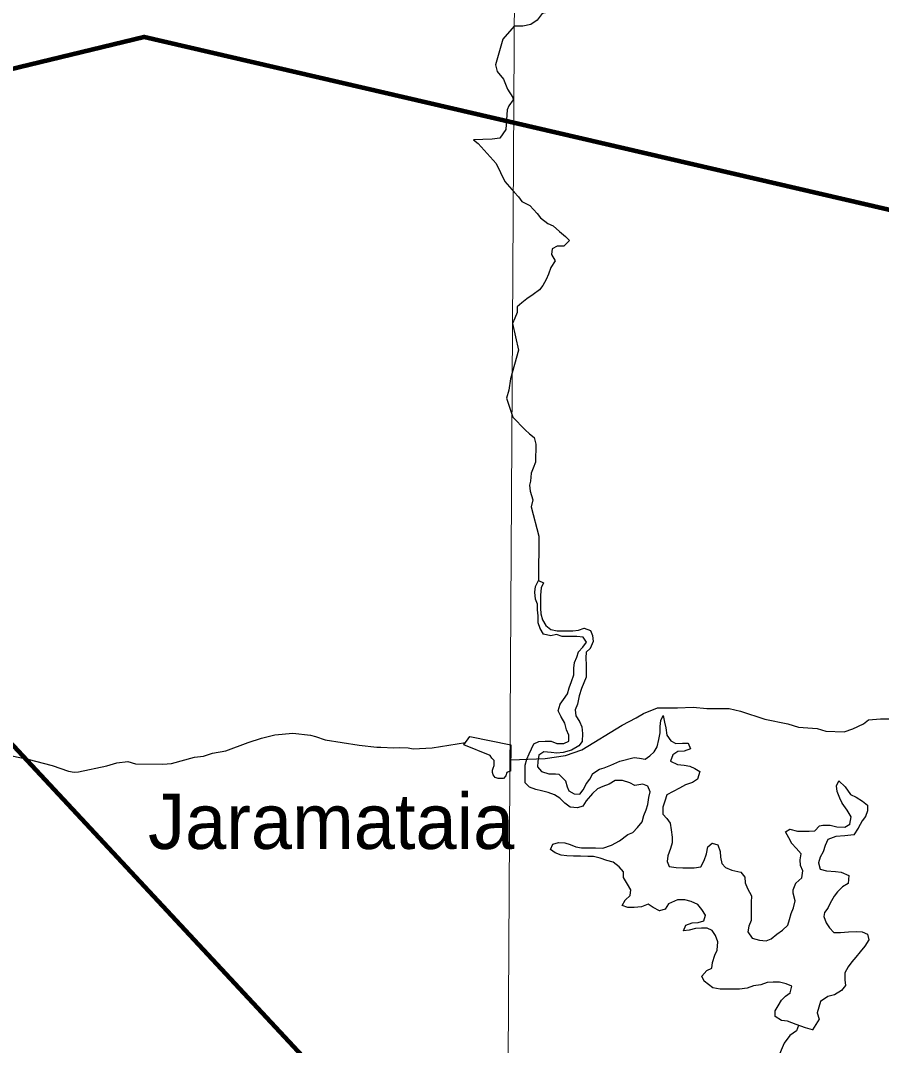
# Model space of a CAD drawing. Extents: x 553962 to 842807, y 8883888 to 9032388.
# Drawn here: x 715039 to 722813, y 8929001 to 8938264 of the extents above; entities that cross this region are included whole.
import ezdxf

# ---------------------------------------------------------------- set-up
doc = ezdxf.new("R2010")
doc.units = 0
doc.header["$LTSCALE"] = 200
for name, color, linetype, lineweight in [('1', 7, 'Continuous', 13), ('12', 7, 'Continuous', 25), ('21', 7, 'Continuous', 25), ('24', 7, 'Continuous', 25), ('9', 7, 'Continuous', 90)]:
    doc.layers.add(name, color=color, linetype=linetype, lineweight=lineweight)
doc.layers.add('41', color=7, linetype='Continuous')

msp = doc.modelspace()

# ---------------------------------------------------------------- linework, layer by layer
at = {"layer": '1'}
msp.add_lwpolyline([(719978.9, 9023574.5), (719561.6, 8949232.2), (719215.6, 8890710.6)], dxfattribs=at)
at = {"layer": '12'}
for points in [[(719465.7, 8931582), (719776.2, 8931594.6), (719960.1, 8931621.3), (720108, 8931671.9), (720470.6, 8931895.4), (720598.2, 8931961.4), (720664.5, 8932002), (720792.1, 8932052.7), (720970.4, 8932052.4), (721113, 8932057.2), (721235.3, 8932046.8), (721439, 8932046.4), (721540.8, 8932020.8), (721759.6, 8931949.1), (721968.3, 8931907.9), (722065, 8931877.2), (722233.1, 8931866.7), (722309.4, 8931841.1), (722477.5, 8931835.7), (722554, 8931861), (722651, 8931906.7), (722697, 8931942.3), (722804, 8931952.2), (722928.4, 8931953)], [(716324.2, 8931543.6), (716403.5, 8931548.6), (716611, 8931605.6), (716690.2, 8931616.7), (716773.7, 8931642.7), (716891.8, 8931664.4), (717093.4, 8931739.1), (717215.6, 8931777.9), (717335.2, 8931806.9), (717497.8, 8931823.2), (717656.3, 8931805.2), (717701.6, 8931794.1), (717788.3, 8931763.5), (718097.5, 8931715.5), (718256.9, 8931697.3), (718293.2, 8931696)], [(718293.2, 8931696), (718411.2, 8931691.7), (718463.6, 8931694.9), (718539.5, 8931689.8), (718584.8, 8931680.8), (718757, 8931689.8), (719057.1, 8931737.7)], [(714667.4, 8931678.5), (715103.5, 8931588.9), (715323.4, 8931530.2), (715472.8, 8931481.2), (715522.4, 8931471.9), (715561.6, 8931473.7), (715819.4, 8931527.1), (715907.5, 8931556.1), (716007, 8931568.4), (716078.4, 8931547.1), (716324.2, 8931543.6)]]:
    msp.add_lwpolyline(points, dxfattribs=at)
at = {"layer": '21'}
msp.add_lwpolyline([(719466.9, 8931717.9), (719464.5, 8931480.1), (719451.4, 8931477.4), (719431, 8931467.2), (719420.8, 8931436.5), (719400.5, 8931413.5), (719380.2, 8931413.5), (719352.2, 8931413.5), (719324.2, 8931423.7), (719306.3, 8931446.7), (719301.3, 8931467.1), (719301.2, 8931487.6), (719306.3, 8931508), (719316.5, 8931531.1), (719316.5, 8931554.1), (719316.5, 8931577.1), (719296.1, 8931597.5), (719278.3, 8931620.5), (719041.6, 8931717.6), (719097.6, 8931791.8)], close=True, dxfattribs=at)
at = {"layer": '24'}
for points in [[(720060.8, 8938559.8), (720055.8, 8938559.8), (719994.6, 8938534.7), (719948.5, 8938494.2), (719922.7, 8938443.5), (719881.3, 8938336.8), (719825.4, 8938342.2), (719749, 8938327.4), (719702.8, 8938266.6), (719646.6, 8938226.2), (719575.3, 8938211.3), (719495.9, 8938211.8)], [(719495.9, 8938211.8), (719394.7, 8938096.4), (719328.4, 8937863.4), (719342.1, 8937802.6), (719401.1, 8937732.2), (719437, 8937644.3), (719483.8, 8937567.5), (719487.5, 8937545.9), (719449.3, 8937492.5), (719434.6, 8937455.6), (719420.2, 8937279.4), (719367.4, 8937201.3), (719297.2, 8937190.5), (719130.2, 8937185.6)], [(719130.2, 8937185.6), (719170.7, 8937152.3), (719333.3, 8936971.3), (719410.8, 8936807.6), (719495, 8936711.2)], [(719495, 8936711.2), (719536.3, 8936669.7), (719566.5, 8936628.7), (719637.5, 8936592.7), (719703.1, 8936520.9), (719733.3, 8936480), (719799.1, 8936428.7), (719849.8, 8936408), (719905.4, 8936356.8), (719961, 8936310.6), (719996.4, 8936274.7), (719945.2, 8936224.1), (719884.2, 8936224.5), (719838.2, 8936199.3), (719832.8, 8936148.4), (719868, 8936092.2), (719826.9, 8936031.3), (719806.1, 8935970.3), (719785.5, 8935924.6), (719754.6, 8935868.8), (719723.8, 8935828.3), (719667.5, 8935787.9), (719611.3, 8935747.5), (719565.3, 8935712.1), (719524.3, 8935676.7), (719524, 8935625.8), (719503.3, 8935575), (719482.6, 8935524.2), (719536.9, 8935284.5)], [(719536.9, 8935284.5), (719464.5, 8935025.4), (719447.8, 8934924.5), (719426.1, 8934849.8), (719483, 8934679.3)], [(719483, 8934679.3), (719595.3, 8934563.2), (719635.8, 8934527.3), (719676.2, 8934496.5), (719691.1, 8934435.3), (719690.7, 8934384.4), (719690.3, 8934323.2), (719690, 8934272.3), (719669.2, 8934217.6), (719651.2, 8934174.2), (719643, 8934099.5), (719634.9, 8934064), (719642.2, 8934009.8), (719665.6, 8933932.1), (719651.2, 8933868.8), (719718.1, 8933604.6), (719714.8, 8933203.5)], [(720541.5, 8931374.6), (720475.5, 8931395.4), (720409.4, 8931395.9), (720353.4, 8931360.9), (720298.5, 8931340.7), (720249.5, 8931320.4), (720203.3, 8931277.1), (720145.5, 8931210.6), (720116.7, 8931164.4), (720066.9, 8931148.5), (720000.8, 8931154), (719955.3, 8931189.9), (719909.8, 8931236.1), (719859.2, 8931266.9), (719803.4, 8931287.7), (719742.5, 8931303.4), (719691.7, 8931313.9), (719635.9, 8931334.6), (719595.5, 8931375.6), (719595.8, 8931426.6), (719596.2, 8931482.6), (719596.6, 8931533.5), (719612.2, 8931589.4), (719632.8, 8931635.2), (719653.5, 8931680.9), (719674.2, 8931726.6), (719720.1, 8931746.7), (719776.1, 8931751.4), (719832, 8931751), (719882.7, 8931730.3), (719943.8, 8931729.9), (719989.7, 8931750), (719990.1, 8931806.1), (719970, 8931852), (719955.2, 8931913.3), (719920, 8931969.5), (719894.9, 8932025.7), (719910.6, 8932086.7), (719941.4, 8932127.3), (719977.3, 8932178), (719993, 8932233.9), (720013.7, 8932289.8), (720034.5, 8932350.8), (720034.9, 8932411.9), (720040.3, 8932462.8), (720061, 8932508.6), (720076.6, 8932559.4), (720117.6, 8932599.9), (720148.4, 8932645.5), (720118.2, 8932691.6), (720062.3, 8932697), (719991.1, 8932697.5), (719930.1, 8932697.9), (719879.3, 8932713.5), (719828.4, 8932703.6), (719762.4, 8932719.3), (719732.2, 8932770.4), (719712.2, 8932821.5), (719712.6, 8932882.7), (719707.9, 8932938.7), (719708.3, 8932989.6), (719688.2, 8933035.6), (719683.6, 8933096.8), (719689, 8933147.7), (719714.8, 8933203.5), (719760.5, 8933182.9), (719739.8, 8933137.2), (719734.3, 8933071), (719733.8, 8933009.9), (719733.5, 8932953.8), (719738.2, 8932902.9), (719753.1, 8932846.7), (719783.2, 8932795.6), (719828.8, 8932759.7), (719884.6, 8932749.1), (719960.9, 8932748.6), (720027.1, 8932748.2), (720078, 8932753), (720129, 8932773), (720184.8, 8932752.3), (720204.8, 8932706.3), (720209.5, 8932650.2), (720183.6, 8932589.3), (720147.8, 8932553.8), (720142.3, 8932502.9), (720147, 8932436.7), (720146.6, 8932385.8), (720146.2, 8932329.7), (720125.6, 8932278.9), (720104.8, 8932228.1), (720084.1, 8932162), (720068.3, 8932085.7), (720047.6, 8932034.9), (720052.3, 8931978.8), (720087.5, 8931927.7), (720107.6, 8931881.7), (720112.2, 8931820.6), (720111.7, 8931749.2), (720080.9, 8931708.7), (720014.5, 8931668.4), (719938.1, 8931648.5)], [(719938.1, 8931648.5), (719882.1, 8931643.8), (719831.3, 8931649.2), (719765.2, 8931654.7), (719719.2, 8931624.4), (719708.7, 8931568.5), (719708.3, 8931517.5), (719743.7, 8931476.5), (719809.6, 8931455.7), (719870.7, 8931455.3), (719899.8, 8931451.2), (719959.3, 8931391.6), (719974.2, 8931339.4), (719989.1, 8931302.2), (720037.3, 8931276), (720088.1, 8931270.6), (720118.9, 8931311.1), (720149.8, 8931367), (720180.6, 8931407.5), (720206.4, 8931458.3), (720267.7, 8931498.7), (720309.2, 8931510.9), (720368.7, 8931533.2), (720450.6, 8931570.5), (720578.7, 8931603.6), (720629.5, 8931598.2), (720680.3, 8931587.7), (720721.2, 8931618), (720762.1, 8931653.4), (720787.8, 8931699.1), (720803.6, 8931765.2), (720814.2, 8931826.2), (720814.5, 8931882.3), (720820, 8931938.3), (720840.7, 8931984), (720855.5, 8931922.8), (720865.3, 8931871.8), (720875.1, 8931805.5), (720910.3, 8931754.3), (720955.9, 8931728.6), (721017, 8931733.3), (721067.8, 8931732.9), (721087.8, 8931681.9), (721031.7, 8931661.8), (720975.8, 8931657.1), (720929.8, 8931626.8), (720909, 8931570.9), (720969.9, 8931540), (721030.9, 8931534.5), (721081.7, 8931524), (721127.3, 8931503.3), (721172.9, 8931477.6), (721152, 8931406.4), (721106.1, 8931376.1), (721044.9, 8931356.1), (720988.7, 8931325.9), (720932.6, 8931295.7), (720876.4, 8931265.5), (720855.7, 8931209.6), (720840.1, 8931153.7), (720839.6, 8931092.6), (720875, 8931051.6), (720905.2, 8931010.6), (720914.9, 8930949.5), (720924.7, 8930883.2), (720924.3, 8930832.2), (720908.7, 8930781.4), (720882.8, 8930715.3), (720877.4, 8930664.4), (720897.4, 8930618.5), (720958.4, 8930607.9), (721019.4, 8930607.5), (721070.3, 8930607.2), (721121.1, 8930606.8), (721182.2, 8930616.6), (721213.1, 8930672.5), (721233.9, 8930733.5), (721244.5, 8930794.5), (721285.4, 8930829.9), (721336.2, 8930814.3), (721356.1, 8930753.1), (721360.8, 8930702.1), (721370.6, 8930646), (721406, 8930610.1), (721461.7, 8930584.3), (721543, 8930568.5), (721578.3, 8930522.4), (721583, 8930471.4), (721603, 8930420.4), (721638.2, 8930353.9), (721637.8, 8930292.8), (721637.4, 8930241.9), (721637.1, 8930190.9), (721636.6, 8930129.8), (721615.9, 8930079), (721605.4, 8930028.1), (721645.7, 8929971.8), (721711.7, 8929951), (721772.7, 8929945.6), (721818.6, 8929965.6), (721869.7, 8930006.1)], [(722189.3, 8929143.2), (722128.4, 8929158.8), (722042.1, 8929189.9), (721966.1, 8929221), (721910.2, 8929226.4), (721854.5, 8929262.5), (721854.8, 8929313.4), (721880.6, 8929359.1), (721911.4, 8929409.8), (721947.3, 8929445.2), (721988.2, 8929475.5), (722003.8, 8929536.6), (721953.1, 8929557.3), (721892.2, 8929572.9), (721836.2, 8929573.3), (721780.3, 8929568.6), (721724.2, 8929548.6), (721658, 8929538.8), (721601.9, 8929518.8), (721530.6, 8929509), (721474.7, 8929509.4), (721418.7, 8929509.8), (721357.7, 8929510.2), (721291.7, 8929520.8), (721251.2, 8929551.6), (721210.7, 8929582.4), (721190.7, 8929628.4), (721236.8, 8929679), (721282.7, 8929699.1), (721288.2, 8929750), (721309, 8929816.1), (721329.6, 8929861.8), (721335.2, 8929938.2), (721315.3, 8929994.3), (721285.1, 8930040.4), (721239.4, 8930061), (721188.6, 8930061.4), (721132.6, 8930056.6), (721076.5, 8930041.7), (721025.6, 8930036.9), (721046.3, 8930087.8), (721102.4, 8930107.8), (721158.4, 8930112.5), (721209.4, 8930127.5), (721225, 8930178.3), (721189.7, 8930229.5), (721154.4, 8930275.5), (721093.6, 8930301.4), (721037.7, 8930317), (720971.6, 8930317.4), (720890, 8930282.3), (720859.1, 8930231.6), (720808.2, 8930216.6), (720752.4, 8930247.6), (720706.9, 8930278.4), (720645.7, 8930253.3), (720579.5, 8930248.7), (720523.6, 8930249), (720472.8, 8930264.6), (720498.6, 8930315.4), (720544.7, 8930355.8), (720550.1, 8930406.8), (720519.9, 8930457.9), (720484.7, 8930519.2), (720485.1, 8930570.2), (720444.7, 8930616.3), (720389.1, 8930657.4), (720333.2, 8930673), (720272.3, 8930693.8), (720211.4, 8930709.5), (720160.5, 8930709.8), (720094.4, 8930710.2), (720033.4, 8930710.6), (719972.4, 8930716.1), (719921.6, 8930721.5), (719865.8, 8930742.2), (719825.3, 8930773.1), (719845.9, 8930818.8), (719896.9, 8930833.7), (719952.8, 8930833.4), (720003.6, 8930817.8), (720054.3, 8930797.1), (720105.1, 8930786.6), (720166.2, 8930786.2), (720232.3, 8930785.7), (720298.4, 8930785.3), (720374.8, 8930810.3), (720446.3, 8930850.6), (720523, 8930906.1), (720568.9, 8930926.2), (720609.9, 8930971.8), (720651, 8931022.5), (720666.6, 8931078.4), (720687.3, 8931129.2), (720702.9, 8931180), (720713.5, 8931241.1), (720724, 8931292), (720704, 8931343), (720658.4, 8931363.7), (720587.1, 8931348.9), (720541.5, 8931374.6)], [(721869.7, 8930006.1), (721920.8, 8930041.4), (721966.9, 8930086.9), (721982.5, 8930137.8), (721998.2, 8930193.7), (722018.9, 8930244.5), (722035.3, 8930306.7), (722014.7, 8930377), (722015.4, 8930406.4), (722040.8, 8930468.5), (722095, 8930516.1), (722102.6, 8930580.2), (722082.5, 8930626.2), (722077.8, 8930677.1), (722088.4, 8930733.1), (722042.9, 8930784.3), (722002.5, 8930825.3), (721977.5, 8930876.4), (721947.3, 8930932.7), (721985.5, 8930954.9), (722054.2, 8930937.1), (722105, 8930936.7), (722161, 8930936.4), (722211.9, 8930941.1), (722254.4, 8930984.8), (722283.4, 8930991.6), (722349.5, 8930991.2), (722410.5, 8930975.5), (722481.7, 8930975.1), (722527.6, 8931000.2), (722538.2, 8931066.4), (722503.1, 8931127.7), (722457.7, 8931189.2), (722437.7, 8931235.1), (722412.7, 8931296.4), (722407.9, 8931347.4), (722428.6, 8931393.1), (722484.1, 8931336.7), (722534.6, 8931270.2), (722585.2, 8931244.4), (722640.9, 8931208.4), (722686.5, 8931172.4), (722686.1, 8931121.5), (722670.5, 8931070.6), (722639.7, 8931030.1), (722603.7, 8930964.1), (722562.5, 8930903.2), (722483.5, 8930896.6), (722400.2, 8930890.6), (722328.7, 8930860.8), (722304.9, 8930807.2), (722286.8, 8930752.2), (722261.1, 8930701.4), (722245.5, 8930650.6), (722260.3, 8930594.4), (722316.2, 8930578.8), (722397.5, 8930573.2), (722448.3, 8930567.8), (722519.3, 8930536.8), (722513.8, 8930465.5), (722462.7, 8930435.2), (722416.6, 8930389.7), (722385.8, 8930349.1), (722349.8, 8930288.2), (722329.1, 8930242.5), (722298.3, 8930202), (722294.2, 8930167.1), (722313, 8930110.2), (722343.2, 8930064.2), (722383.6, 8930023.1), (722444.6, 8930022.8), (722515.8, 8930027.4), (722587.1, 8930032), (722637.9, 8930026.6), (722688.6, 8930005.9), (722698.4, 8929954.9), (722662.5, 8929899.1), (722621.4, 8929848.4), (722580.4, 8929797.8), (722544.5, 8929757.2), (722513.7, 8929711.6), (722482.8, 8929655.8), (722482.3, 8929594.6), (722487.1, 8929543.7), (722451.2, 8929498), (722389.8, 8929457.7), (722328.7, 8929442.8), (722262.3, 8929397.4), (722246.7, 8929346.5), (722231.1, 8929295.7), (722251, 8929239.5), (722189.3, 8929143.2)], [(722065, 8929181.7), (722047.1, 8929132.1), (721985.8, 8929091.8), (721934.5, 8929020.8), (721908.6, 8928959.8), (721882.8, 8928898.9), (721862, 8928837.9), (721836.2, 8928792.2), (721826.6, 8928771.5)]]:
    msp.add_lwpolyline(points, dxfattribs=at)
at = {"layer": '24', "lineweight": 13}
for points in [[(720541.5, 8931374.6), (720475.5, 8931395.4), (720409.4, 8931395.9), (720353.4, 8931360.9), (720298.5, 8931340.7), (720249.5, 8931320.4), (720203.3, 8931277.1), (720145.5, 8931210.6), (720116.7, 8931164.4), (720066.9, 8931148.5), (720000.8, 8931154), (719955.3, 8931189.9), (719909.8, 8931236.1), (719859.2, 8931266.9), (719803.4, 8931287.7), (719742.5, 8931303.4), (719691.7, 8931313.9), (719635.9, 8931334.6), (719595.5, 8931375.6), (719595.8, 8931426.6), (719596.2, 8931482.6), (719596.6, 8931533.5), (719612.2, 8931589.4), (719632.8, 8931635.2), (719653.5, 8931680.9), (719674.2, 8931726.6), (719720.1, 8931746.7), (719776.1, 8931751.4), (719832, 8931751), (719882.7, 8931730.3), (719943.8, 8931729.9), (719989.7, 8931750), (719990.1, 8931806.1), (719970, 8931852), (719955.2, 8931913.3), (719920, 8931969.5), (719894.9, 8932025.7), (719910.6, 8932086.7), (719941.4, 8932127.3), (719977.3, 8932178), (719993, 8932233.9), (720013.7, 8932289.8), (720034.5, 8932350.8), (720034.9, 8932411.9), (720040.3, 8932462.8), (720061, 8932508.6), (720076.6, 8932559.4), (720117.6, 8932599.9), (720148.4, 8932645.5), (720118.2, 8932691.6), (720062.3, 8932697), (719991.1, 8932697.5), (719930.1, 8932697.9), (719879.3, 8932713.5), (719828.4, 8932703.6), (719762.4, 8932719.3), (719732.2, 8932770.4), (719712.2, 8932821.5), (719712.6, 8932882.7), (719707.9, 8932938.7), (719708.3, 8932989.6), (719688.2, 8933035.6), (719683.6, 8933096.8), (719689, 8933147.7), (719714.8, 8933203.5), (719760.5, 8933182.9), (719739.8, 8933137.2), (719734.3, 8933071), (719733.8, 8933009.9), (719733.5, 8932953.8), (719738.2, 8932902.9), (719753.1, 8932846.7), (719783.2, 8932795.6), (719828.8, 8932759.7), (719884.6, 8932749.1), (719960.9, 8932748.6), (720027.1, 8932748.2), (720078, 8932753), (720129, 8932773), (720184.8, 8932752.3), (720204.8, 8932706.3), (720209.5, 8932650.2), (720183.6, 8932589.3), (720147.8, 8932553.8), (720142.3, 8932502.9), (720147, 8932436.7), (720146.6, 8932385.8), (720146.2, 8932329.7), (720125.6, 8932278.9), (720104.8, 8932228.1), (720084.1, 8932162), (720068.3, 8932085.7), (720047.6, 8932034.9), (720052.3, 8931978.8), (720087.5, 8931927.7), (720107.6, 8931881.7), (720112.2, 8931820.6), (720111.7, 8931749.2), (720080.9, 8931708.7), (720014.5, 8931668.4), (719938.1, 8931648.5)], [(719938.1, 8931648.5), (719882.1, 8931643.8), (719831.3, 8931649.2), (719765.2, 8931654.7), (719719.2, 8931624.4), (719708.7, 8931568.5), (719708.3, 8931517.5), (719743.7, 8931476.5), (719809.6, 8931455.7), (719870.7, 8931455.3), (719899.8, 8931451.2), (719959.3, 8931391.6), (719974.2, 8931339.4), (719989.1, 8931302.2), (720037.3, 8931276), (720088.1, 8931270.6), (720118.9, 8931311.1), (720149.8, 8931367), (720180.6, 8931407.5), (720206.4, 8931458.3), (720267.7, 8931498.7), (720309.2, 8931510.9), (720368.7, 8931533.2), (720450.6, 8931570.5), (720578.7, 8931603.6), (720629.5, 8931598.2), (720680.3, 8931587.7), (720721.2, 8931618), (720762.1, 8931653.4), (720787.8, 8931699.1), (720803.6, 8931765.2), (720814.2, 8931826.2), (720814.5, 8931882.3), (720820, 8931938.3), (720840.7, 8931984), (720855.5, 8931922.8), (720865.3, 8931871.8), (720875.1, 8931805.5), (720910.3, 8931754.3), (720955.9, 8931728.6), (721017, 8931733.3), (721067.8, 8931732.9), (721087.8, 8931681.9), (721031.7, 8931661.8), (720975.8, 8931657.1), (720929.8, 8931626.8), (720909, 8931570.9), (720969.9, 8931540), (721030.9, 8931534.5), (721081.7, 8931524), (721127.3, 8931503.3), (721172.9, 8931477.6), (721152, 8931406.4), (721106.1, 8931376.1), (721044.9, 8931356.1), (720988.7, 8931325.9), (720932.6, 8931295.7), (720876.4, 8931265.5), (720855.7, 8931209.6), (720840.1, 8931153.7), (720839.6, 8931092.6), (720875, 8931051.6), (720905.2, 8931010.6), (720914.9, 8930949.5), (720924.7, 8930883.2), (720924.3, 8930832.2), (720908.7, 8930781.4), (720882.8, 8930715.3), (720877.4, 8930664.4), (720897.4, 8930618.5), (720958.4, 8930607.9), (721019.4, 8930607.5), (721070.3, 8930607.2), (721121.1, 8930606.8), (721182.2, 8930616.6), (721213.1, 8930672.5), (721233.9, 8930733.5), (721244.5, 8930794.5), (721285.4, 8930829.9), (721336.2, 8930814.3), (721356.1, 8930753.1), (721360.8, 8930702.1), (721370.6, 8930646), (721406, 8930610.1), (721461.7, 8930584.3), (721543, 8930568.5), (721578.3, 8930522.4), (721583, 8930471.4), (721603, 8930420.4), (721638.2, 8930353.9), (721637.8, 8930292.8), (721637.4, 8930241.9), (721637.1, 8930190.9), (721636.6, 8930129.8), (721615.9, 8930079), (721605.4, 8930028.1), (721645.7, 8929971.8), (721711.7, 8929951), (721772.7, 8929945.6), (721818.6, 8929965.6), (721869.7, 8930006.1)], [(722189.3, 8929143.2), (722128.4, 8929158.8), (722042.1, 8929189.9), (721966.1, 8929221), (721910.2, 8929226.4), (721854.5, 8929262.5), (721854.8, 8929313.4), (721880.6, 8929359.1), (721911.4, 8929409.8), (721947.3, 8929445.2), (721988.2, 8929475.5), (722003.8, 8929536.6), (721953.1, 8929557.3), (721892.2, 8929572.9), (721836.2, 8929573.3), (721780.3, 8929568.6), (721724.2, 8929548.6), (721658, 8929538.8), (721601.9, 8929518.8), (721530.6, 8929509), (721474.7, 8929509.4), (721418.7, 8929509.8), (721357.7, 8929510.2), (721291.7, 8929520.8), (721251.2, 8929551.6), (721210.7, 8929582.4), (721190.7, 8929628.4), (721236.8, 8929679), (721282.7, 8929699.1), (721288.2, 8929750), (721309, 8929816.1), (721329.6, 8929861.8), (721335.2, 8929938.2), (721315.3, 8929994.3), (721285.1, 8930040.4), (721239.4, 8930061), (721188.6, 8930061.4), (721132.6, 8930056.6), (721076.5, 8930041.7), (721025.6, 8930036.9), (721046.3, 8930087.8), (721102.4, 8930107.8), (721158.4, 8930112.5), (721209.4, 8930127.5), (721225, 8930178.3), (721189.7, 8930229.5), (721154.4, 8930275.5), (721093.6, 8930301.4), (721037.7, 8930317), (720971.6, 8930317.4), (720890, 8930282.3), (720859.1, 8930231.6), (720808.2, 8930216.6), (720752.4, 8930247.6), (720706.9, 8930278.4), (720645.7, 8930253.3), (720579.5, 8930248.7), (720523.6, 8930249), (720472.8, 8930264.6), (720498.6, 8930315.4), (720544.7, 8930355.8), (720550.1, 8930406.8), (720519.9, 8930457.9), (720484.7, 8930519.2), (720485.1, 8930570.2), (720444.7, 8930616.3), (720389.1, 8930657.4), (720333.2, 8930673), (720272.3, 8930693.8), (720211.4, 8930709.5), (720160.5, 8930709.8), (720094.4, 8930710.2), (720033.4, 8930710.6), (719972.4, 8930716.1), (719921.6, 8930721.5), (719865.8, 8930742.2), (719825.3, 8930773.1), (719845.9, 8930818.8), (719896.9, 8930833.7), (719952.8, 8930833.4), (720003.6, 8930817.8), (720054.3, 8930797.1), (720105.1, 8930786.6), (720166.2, 8930786.2), (720232.3, 8930785.7), (720298.4, 8930785.3), (720374.8, 8930810.3), (720446.3, 8930850.6), (720523, 8930906.1), (720568.9, 8930926.2), (720609.9, 8930971.8), (720651, 8931022.5), (720666.6, 8931078.4), (720687.3, 8931129.2), (720702.9, 8931180), (720713.5, 8931241.1), (720724, 8931292), (720704, 8931343), (720658.4, 8931363.7), (720587.1, 8931348.9), (720541.5, 8931374.6)], [(721869.7, 8930006.1), (721920.8, 8930041.4), (721966.9, 8930086.9), (721982.5, 8930137.8), (721998.2, 8930193.7), (722018.9, 8930244.5), (722035.3, 8930306.7), (722014.7, 8930377), (722015.4, 8930406.4), (722040.8, 8930468.5), (722095, 8930516.1), (722102.6, 8930580.2), (722082.5, 8930626.2), (722077.8, 8930677.1), (722088.4, 8930733.1), (722042.9, 8930784.3), (722002.5, 8930825.3), (721977.5, 8930876.4), (721947.3, 8930932.7), (721985.5, 8930954.9), (722054.2, 8930937.1), (722105, 8930936.7), (722161, 8930936.4), (722211.9, 8930941.1), (722254.4, 8930984.8), (722283.4, 8930991.6), (722349.5, 8930991.2), (722410.5, 8930975.5), (722481.7, 8930975.1), (722527.6, 8931000.2), (722538.2, 8931066.4), (722503.1, 8931127.7), (722457.7, 8931189.2), (722437.7, 8931235.1), (722412.7, 8931296.4), (722407.9, 8931347.4), (722428.6, 8931393.1), (722484.1, 8931336.7), (722534.6, 8931270.2), (722585.2, 8931244.4), (722640.9, 8931208.4), (722686.5, 8931172.4), (722686.1, 8931121.5), (722670.5, 8931070.6), (722639.7, 8931030.1), (722603.7, 8930964.1), (722562.5, 8930903.2), (722483.5, 8930896.6), (722400.2, 8930890.6), (722328.7, 8930860.8), (722304.9, 8930807.2), (722286.8, 8930752.2), (722261.1, 8930701.4), (722245.5, 8930650.6), (722260.3, 8930594.4), (722316.2, 8930578.8), (722397.5, 8930573.2), (722448.3, 8930567.8), (722519.3, 8930536.8), (722513.8, 8930465.5), (722462.7, 8930435.2), (722416.6, 8930389.7), (722385.8, 8930349.1), (722349.8, 8930288.2), (722329.1, 8930242.5), (722298.3, 8930202), (722294.2, 8930167.1), (722313, 8930110.2), (722343.2, 8930064.2), (722383.6, 8930023.1), (722444.6, 8930022.8), (722515.8, 8930027.4), (722587.1, 8930032), (722637.9, 8930026.6), (722688.6, 8930005.9), (722698.4, 8929954.9), (722662.5, 8929899.1), (722621.4, 8929848.4), (722580.4, 8929797.8), (722544.5, 8929757.2), (722513.7, 8929711.6), (722482.8, 8929655.8), (722482.3, 8929594.6), (722487.1, 8929543.7), (722451.2, 8929498), (722389.8, 8929457.7), (722328.7, 8929442.8), (722262.3, 8929397.4), (722246.7, 8929346.5), (722231.1, 8929295.7), (722251, 8929239.5), (722189.3, 8929143.2)]]:
    msp.add_lwpolyline(points, dxfattribs=at)
at = {"layer": '9'}
msp.add_line((710319.1, 8936704.6), (720989.4, 8925252.2), dxfattribs=at)
msp.add_lwpolyline([(696242, 8937672.8), (702061.8, 8937200.5), (702208.9, 8933124.7), (710319.1, 8936704.6), (716154, 8938115.2), (724825.2, 8936103.1), (730092.7, 8935013.9)], dxfattribs=at)

# ---------------------------------------------------------------- texts
at = {"layer": '41'}
msp.add_text('Jaramataia', height=500, dxfattribs=at).set_placement((716190.3, 8930776.7))

doc.saveas('drawing.dxf')
